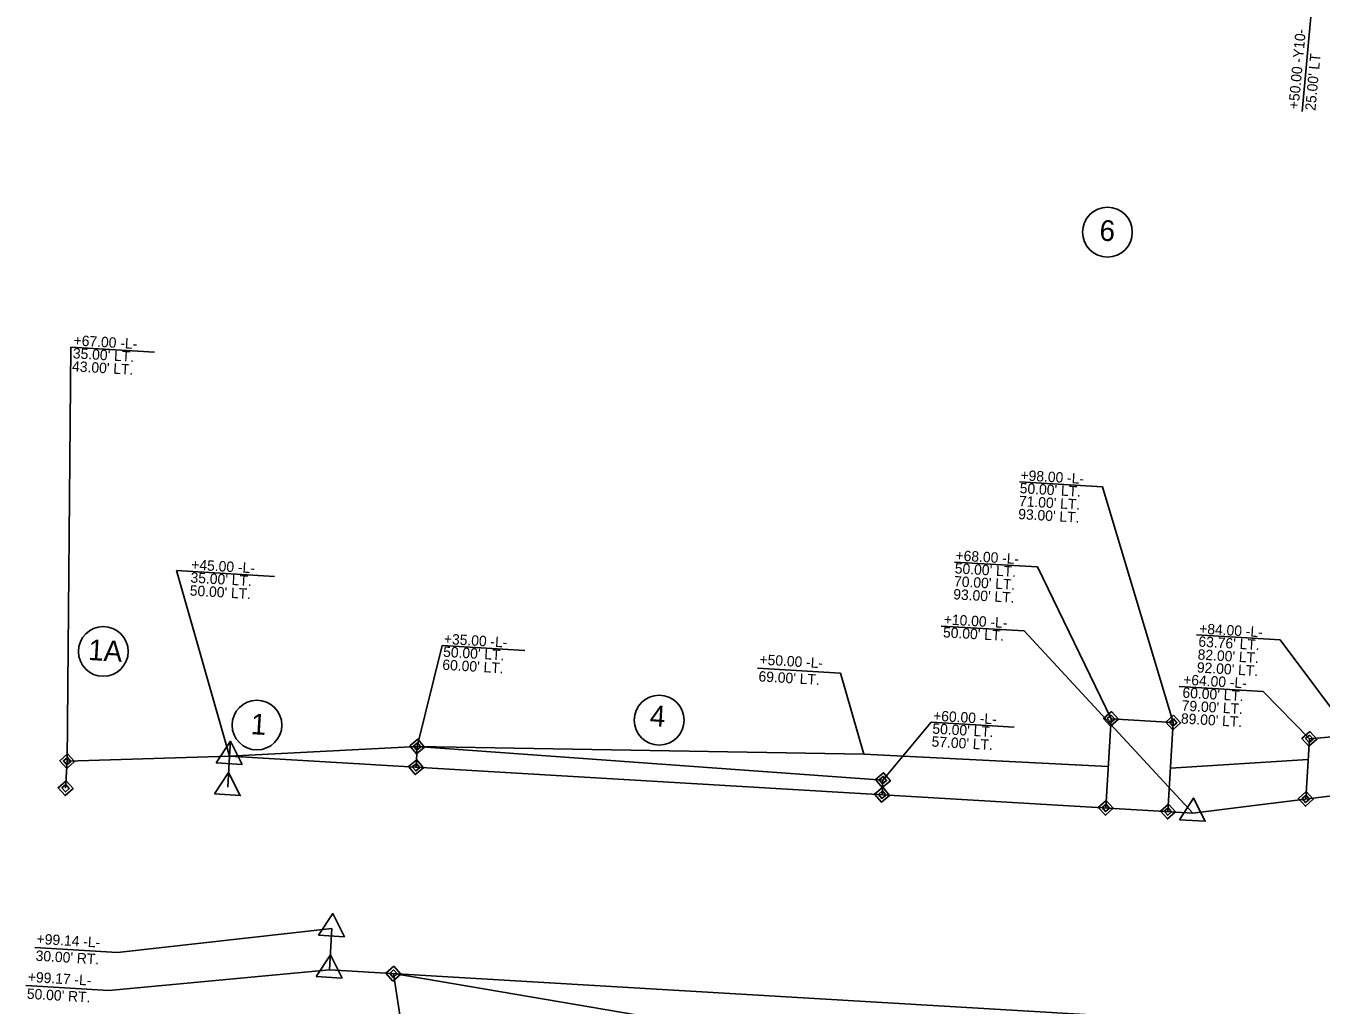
# Model space of a CAD drawing. Extents: x 2010883 to 2014849, y 442000 to 447413.
# Drawn here: x 2011189 to 2011813, y 444960 to 445432 of the extents above; entities that cross this region are included whole.
import ezdxf

# ---------------------------------------------------------------- set-up
doc = ezdxf.new("R2010")
doc.units = 0
for name, color, linetype in [('Prop Easement Construction', 7, 'Continuous'), ('Prop Easement Construction Station Offsets', 7, 'Continuous'), ('Prop Easement Permanent Drainage', 7, 'Continuous'), ('Prop Easement Permanent Drainage Station Offsets', 7, 'Continuous'), ('Prop Easement Permanent Utility', 7, 'Continuous'), ('Prop Easement Permanent Utility Station Offsets', 7, 'Continuous'), ('Prop Parcel Number CELL', 7, 'Continuous'), ('Prop Parcel Number Text', 7, 'Continuous'), ('Prop ROW Marker CELL', 7, 'Continuous'), ('Prop ROW Permanent Easement CELL', 7, 'Continuous'), ('Prop ROW RW Lines', 7, 'Continuous'), ('Prop ROW Station Offsets', 7, 'Continuous')]:
    doc.layers.add(name, color=color, linetype=linetype)

msp = doc.modelspace()

# ---------------------------------------------------------------- linework, layer by layer
at = {"layer": 'Prop Easement Construction'}
for p, q in [((2011287.28, 445079.9), (2011287.7, 445087.11)), ((2011287.28, 445079.9), (2011377.71, 445084.58)), ((2011377.71, 445084.58), (2011592.87, 445080.92)), ((2011592.87, 445080.92), (2011710.72, 445074.97)), ((2011740.73, 445074.2), (2011807.08, 445078.31))]:
    msp.add_line(p, q, dxfattribs=at)
at = {"layer": 'Prop Easement Construction Station Offsets'}
for p, q in [((2011804.21, 445390.84), (2011808.88, 445441.67)), ((2011541.72, 445122.34), (2011581.65, 445119.98)), ((2011592.87, 445080.92), (2011581.65, 445119.98))]:
    msp.add_line(p, q, dxfattribs=at)
at = {"layer": 'Prop Easement Permanent Drainage'}
for p, q in [((2011807.67, 445088.29), (2011805.96, 445059.34)), ((2011807.67, 445088.29), (2011827.81, 445090.11)), ((2011377.12, 445074.6), (2011377.71, 445084.58)), ((2011377.71, 445084.58), (2011602.14, 445068.35)), ((2011208.23, 445064.52), (2011209, 445077.5)), ((2011209, 445077.5), (2011287.28, 445079.9)), ((2011602.14, 445068.35), (2011601.73, 445061.36))]:
    msp.add_line(p, q, dxfattribs=at)
at = {"layer": 'Prop Easement Permanent Drainage Station Offsets'}
for p, q in [((2011209, 445077.5), (2011210.71, 445277.19)), ((2011210.71, 445277.19), (2011251.16, 445274.8)), ((2011753.2, 445138.42), (2011793.66, 445136.03)), ((2011377.71, 445084.58), (2011389.67, 445133.29)), ((2011389.67, 445133.29), (2011429.6, 445130.93)), ((2011793.66, 445136.03), (2011827.81, 445090.11)), ((2011744.85, 445113.47), (2011785.31, 445111.09)), ((2011785.31, 445111.09), (2011807.67, 445088.29)), ((2011602.14, 445068.35), (2011625.45, 445096.25)), ((2011625.45, 445096.25), (2011665.38, 445093.9))]:
    msp.add_line(p, q, dxfattribs=at)
at = {"layer": 'Prop Easement Permanent Utility'}
for p, q in [((2011709.54, 445055.01), (2011712.07, 445097.93)), ((2011712.07, 445097.93), (2011742.02, 445096.17)), ((2011742.02, 445096.17), (2011739.49, 445053.24)), ((2011366.24, 444975.07), (2011519.97, 444948.98))]:
    msp.add_line(p, q, dxfattribs=at)
at = {"layer": 'Prop Easement Permanent Utility Station Offsets'}
for p, q in [((2011667.95, 445212.16), (2011707.88, 445209.81)), ((2011742.02, 445096.17), (2011707.88, 445209.81)), ((2011636.66, 445173.5), (2011676.59, 445171.15)), ((2011712.07, 445097.93), (2011676.59, 445171.15)), ((2011366.24, 444975.07), (2011375.79, 444912.6))]:
    msp.add_line(p, q, dxfattribs=at)
at = {"layer": 'Prop Parcel Number CELL'}
for p, q in [((2011710.33, 445332.57), (2011710.33, 445332.57)), ((2011226.41, 445130.44), (2011226.41, 445130.44)), ((2011300.47, 445094.93), (2011300.47, 445094.93)), ((2011494.28, 445097.3), (2011494.28, 445097.3))]:
    msp.add_line(p, q, dxfattribs=at)
for centre in [(2011710.33, 445332.57), (2011226.41, 445130.44), (2011300.47, 445094.93), (2011494.28, 445097.3)]:
    msp.add_circle(centre, 12, dxfattribs=at)
at = {"layer": 'Prop ROW Marker CELL'}
for p, q in [((2011712.07, 445097.93), (2011712.07, 445097.93)), ((2011742.02, 445096.17), (2011742.02, 445096.17)), ((2011807.67, 445088.29), (2011807.67, 445088.29)), ((2011377.71, 445084.58), (2011377.71, 445084.58)), ((2011209, 445077.5), (2011209, 445077.5)), ((2011287.28, 445079.9), (2011287.28, 445079.9)), ((2011377.12, 445074.6), (2011377.12, 445074.6)), ((2011208.23, 445064.52), (2011208.23, 445064.52)), ((2011286.39, 445064.92), (2011286.39, 445064.92)), ((2011602.14, 445068.35), (2011602.14, 445068.35)), ((2011601.73, 445061.36), (2011601.73, 445061.36)), ((2011805.96, 445059.34), (2011805.96, 445059.34)), ((2011709.54, 445055.01), (2011709.54, 445055.01)), ((2011739.49, 445053.24), (2011739.49, 445053.24)), ((2011751.47, 445052.53), (2011751.47, 445052.53)), ((2011336.62, 444996.85), (2011336.62, 444996.85)), ((2011335.47, 444976.88), (2011335.47, 444976.88)), ((2011366.24, 444975.07), (2011366.24, 444975.07))]:
    msp.add_line(p, q, dxfattribs=at)
for points in [[(2011280.82, 445076.67), (2011287.7, 445087.09), (2011293.3, 445075.94)], [(2011279.94, 445061.7), (2011286.82, 445072.11), (2011292.42, 445060.96)], [(2011745.02, 445049.31), (2011751.89, 445059.72), (2011757.5, 445048.57)], [(2011330.17, 444993.62), (2011337.04, 445004.04), (2011342.64, 444992.89)], [(2011329.02, 444973.66), (2011335.89, 444984.07), (2011341.5, 444972.92)]]:
    msp.add_lwpolyline(points, close=True, dxfattribs=at)
at = {"layer": 'Prop ROW Permanent Easement CELL'}
for points in [[(2011712.28, 445101.53), (2011715.67, 445097.72), (2011711.86, 445094.34), (2011708.48, 445098.14)], [(2011712.18, 445099.73), (2011713.87, 445097.83), (2011711.97, 445096.14), (2011710.28, 445098.04)], [(2011742.23, 445099.76), (2011745.61, 445095.95), (2011741.81, 445092.57), (2011738.43, 445096.38)], [(2011742.13, 445097.96), (2011743.82, 445096.06), (2011741.92, 445094.37), (2011740.22, 445096.27)], [(2011374.12, 445084.91), (2011378.04, 445088.17), (2011381.29, 445084.26), (2011377.38, 445081)], [(2011807.88, 445091.88), (2011811.27, 445088.08), (2011807.46, 445084.7), (2011804.08, 445088.5)], [(2011807.78, 445090.09), (2011809.47, 445088.18), (2011807.57, 445086.49), (2011805.87, 445088.4)], [(2011375.92, 445084.75), (2011377.87, 445086.38), (2011379.5, 445084.42), (2011377.54, 445082.79)], [(2011209.21, 445081.09), (2011212.59, 445077.29), (2011208.79, 445073.91), (2011205.41, 445077.71)], [(2011209.1, 445079.3), (2011210.8, 445077.39), (2011208.89, 445075.7), (2011207.2, 445077.61)], [(2011373.54, 445074.93), (2011377.45, 445078.19), (2011380.7, 445074.27), (2011376.79, 445071.02)], [(2011375.33, 445074.77), (2011377.28, 445076.39), (2011378.91, 445074.44), (2011376.96, 445072.81)], [(2011598.56, 445068.68), (2011602.47, 445071.93), (2011605.73, 445068.02), (2011601.81, 445064.76)], [(2011600.35, 445068.51), (2011602.31, 445070.14), (2011603.93, 445068.18), (2011601.98, 445066.56)], [(2011208.45, 445068.12), (2011211.83, 445064.31), (2011208.02, 445060.93), (2011204.64, 445064.73)], [(2011208.34, 445066.32), (2011210.03, 445064.42), (2011208.13, 445062.73), (2011206.44, 445064.63)], [(2011598.15, 445061.69), (2011602.06, 445064.95), (2011605.31, 445061.03), (2011601.4, 445057.78)], [(2011599.94, 445061.53), (2011601.89, 445063.15), (2011603.52, 445061.2), (2011601.57, 445059.57)], [(2011709.75, 445058.6), (2011713.14, 445054.79), (2011709.33, 445051.41), (2011705.95, 445055.22)], [(2011739.7, 445056.83), (2011743.08, 445053.03), (2011739.28, 445049.65), (2011735.9, 445053.45)], [(2011806.18, 445062.93), (2011809.56, 445059.13), (2011805.75, 445055.75), (2011802.37, 445059.55)], [(2011806.07, 445061.14), (2011807.76, 445059.23), (2011805.86, 445057.54), (2011804.17, 445059.45)], [(2011709.65, 445056.8), (2011711.34, 445054.9), (2011709.44, 445053.21), (2011707.75, 445055.11)], [(2011739.6, 445055.04), (2011741.29, 445053.14), (2011739.38, 445051.44), (2011737.69, 445053.35)], [(2011366.46, 444978.66), (2011369.84, 444974.86), (2011366.03, 444971.48), (2011362.65, 444975.28)], [(2011366.35, 444976.87), (2011368.04, 444974.96), (2011366.14, 444973.27), (2011364.45, 444975.18)]]:
    msp.add_lwpolyline(points, close=True, dxfattribs=at)
at = {"layer": 'Prop ROW RW Lines'}
for p, q in [((2011286.39, 445064.92), (2011287.28, 445079.9)), ((2011287.28, 445079.9), (2011751.47, 445052.53)), ((2011751.47, 445052.53), (2011916.2, 445073.02)), ((2011335.47, 444976.88), (2011336.62, 444996.85)), ((2011335.47, 444976.88), (2011767.58, 444951.41))]:
    msp.add_line(p, q, dxfattribs=at)
at = {"layer": 'Prop ROW Station Offsets'}
for p, q in [((2011287.28, 445079.9), (2011261.76, 445169.42)), ((2011261.76, 445169.42), (2011308.92, 445166.64)), ((2011630.24, 445142.67), (2011670.18, 445140.31)), ((2011751.47, 445052.53), (2011670.18, 445140.31)), ((2011336.62, 444996.85), (2011233.28, 444985.3)), ((2011193.35, 444987.66), (2011233.28, 444985.3)), ((2011335.47, 444976.88), (2011229.05, 444966.95)), ((2011189.12, 444969.31), (2011229.05, 444966.95))]:
    msp.add_line(p, q, dxfattribs=at)

# ---------------------------------------------------------------- texts
at = {"layer": 'Prop Easement Construction Station Offsets'}
for s, rotation, p in [('+50.00 -Y10-', 84.74666, (2011802.45, 445391.73)), ("25.00' LT", 84.74666, (2011810.55, 445390.99)), ('+50.00 -L-', 356.62643, (2011542.55, 445124.12)), ("69.00' LT.", 356.62643, (2011542.07, 445116.01))]:
    msp.add_text(s, height=5, rotation=rotation, dxfattribs=at).set_placement(p)
at = {"layer": 'Prop Easement Permanent Drainage Station Offsets'}
for s, p in [('+67.00 -L-', (2011212.01, 445278)), ("35.00' LT.", (2011211.64, 445271.76)), ("43.00' LT.", (2011211.27, 445265.52)), ('+35.00 -L-', (2011390.44, 445134.08)), ('+84.00 -L-', (2011754.45, 445139.02)), ("50.00' LT.", (2011390.08, 445127.85)), ("63.76' LT.", (2011754.08, 445132.78)), ("60.00' LT.", (2011389.71, 445121.61)), ("82.00' LT.", (2011753.71, 445126.54)), ("92.00' LT.", (2011753.34, 445120.3)), ("60.00' LT.", (2011746.38, 445108.17)), ('+64.00 -L-', (2011746.75, 445114.41)), ("79.00' LT.", (2011746.01, 445101.93)), ('+60.00 -L-', (2011626.22, 445097.05)), ("89.00' LT.", (2011745.65, 445095.69)), ("50.00' LT.", (2011625.86, 445090.81)), ("57.00' LT.", (2011625.49, 445084.57))]:
    msp.add_text(s, height=5, rotation=356.62643, dxfattribs=at).set_placement(p)
at = {"layer": 'Prop Easement Permanent Utility Station Offsets'}
for s, p in [('+98.00 -L-', (2011668.33, 445212.98)), ("50.00' LT.", (2011667.96, 445206.74)), ("71.00' LT.", (2011667.59, 445200.5)), ("93.00' LT.", (2011667.23, 445194.26)), ('+68.00 -L-', (2011637.03, 445174.32)), ("50.00' LT.", (2011636.67, 445168.08)), ("70.00' LT.", (2011636.3, 445161.84)), ("93.00' LT.", (2011635.93, 445155.6))]:
    msp.add_text(s, height=5, rotation=356.62643, dxfattribs=at).set_placement(p)
at = {"layer": 'Prop Parcel Number Text'}
for s, p in [('6', (2011706.3, 445328.58)), ('1A', (2011218.97, 445126.34)), ('4', (2011489.61, 445094.53)), ('1', (2011297.29, 445090.57))]:
    msp.add_text(s, height=10, rotation=356.62643, dxfattribs=at).set_placement(p)
at = {"layer": 'Prop ROW Station Offsets'}
for s, p in [('+45.00 -L-', (2011268.71, 445169.88)), ("35.00' LT.", (2011268.34, 445163.64)), ("50.00' LT.", (2011267.98, 445157.4)), ('+10.00 -L-', (2011631.36, 445143.49)), ("50.00' LT.", (2011630.99, 445137.25)), ('+99.14 -L-', (2011194.18, 444989.44)), ("30.00' RT.", (2011193.7, 444981.33)), ('+99.17 -L-', (2011189.95, 444971.09)), ("50.00' RT.", (2011189.47, 444962.98))]:
    msp.add_text(s, height=5, rotation=356.62643, dxfattribs=at).set_placement(p)

doc.saveas('drawing.dxf')
